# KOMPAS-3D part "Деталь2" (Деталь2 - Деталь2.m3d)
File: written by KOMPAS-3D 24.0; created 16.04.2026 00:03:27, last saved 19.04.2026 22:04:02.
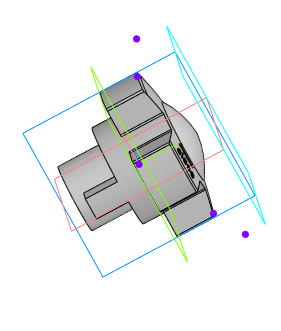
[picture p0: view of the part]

Document properties: Автор: tyuri; Полное имя файла: C:\Работа\VB0000P-T DN X PN 25 Клапан балансировочный DN.ru\DN15\исходные материалы\Деталь2 - Деталь2.m3d

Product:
- Body: Твердое тело1  | qty 1
    Масса: 0.240364
- Part/product: Деталь2
    Масса: 0.240364
    additional columns: Типовые

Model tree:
1. Твердое тело1  (labels: Твердое тело1)
2. Смещенная плоскость:1
     Расстояние = 25
3. Эскиз:2
4. Элемент вращения:1
     Угол 1 = 360
5. Эскиз:3  (with: Ребро.Элемент вращения:1)  (labels: Грань.Твердое тело1; Ребро.Твердое тело1)
6. Элемент вращения:2
     Угол 1 = 360
7. Эскиз:4  (with: Ребро.Элемент вращения:1)  (labels: Грань.Твердое тело1)
8. Элемент выдавливания:2  (with: Грань.Элемент вращения:1)
     Расстояние 1 = 0.481617
9. Эскиз:5  (with: Ребро.Элемент вращения:1)
10. Элемент вращения:3
     Угол 1 = 360
11. Эскиз:12  (labels: Грань.Твердое тело1; Ребро.Твердое тело1)
12. Элемент выдавливания:4  (labels: Грань.Твердое тело1)
     Расстояние 2 = 10
13. Эскиз:14  (with: Грань.Элемент выдавливания:4)
14. Элемент выдавливания:5
     Расстояние 1 = 20
15. Эскиз:15  (with: Грань.Элемент выдавливания:4, Ребро.Элемент выдавливания:5)  (labels: Ребро.Твердое тело1)
16. Элемент выдавливания:6
     Расстояние 1 = 15
17. Эскиз:16
18. Эскиз:17
19. Элемент выдавливания:7  (with: Грань.Элемент вращения:1)
     Расстояние 1 = 23.9129; Смещение 1 = 0.1
20. Точка:1  (with: Ребро.Элемент вращения:1)
     X = 34; Y = 17.077; Смещение (% от длины кривой) = 50
21. Точка:2  (with: Ребро.Элемент вращения:1)
     X = -34; Y = 17.077; Смещение (% от длины кривой) = 50
22. Масштабирование:1
23. Масштабирование : Твердое тело1  (labels: Масштабирование : Точка:1; Масштабирование : Точка:2)
     Масштаб по оси Х = 1; Масштаб по оси Y = 1; Масштаб по оси Z = 1; Коэффициент = 0.7

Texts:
  GOST 26.020 Pr3
  Масштабирование : Вершина.Начало координат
